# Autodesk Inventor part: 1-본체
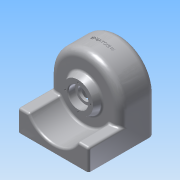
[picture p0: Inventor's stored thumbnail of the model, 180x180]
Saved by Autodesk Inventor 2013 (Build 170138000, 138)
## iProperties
Created: 2015-02
Part Number: 1-본체
Material: 알루미늄 6061
Document SubType Name: Modeling
Designer: Administrator
Density: 2.40731 g/cm^3
Mass: 511.244 g
Surface Area: 706.56 cm^2
Volume: 212.371 cm^3
Author: Administrator
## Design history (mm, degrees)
sketch "스케치1"
  geometry: L1 (-50, -50)-(50, -50); L2 (50, -50)-(50, 0); L3 (-50, 0)-(-50, -50); A1 r 50 centre (0, 0) between (50, 0) and (-50, 0); 1 further point
  constraints: 6 end point, 2 perpendicular, 2 point on circle, 1 centre point, 1 coincident, 1 horizontal, 1 parallel, 1 tangent
  dimensions: "d0" = 50 radius of A1; "d2" = 50 distance from line of L1 A1.centre
extrude "돌출1" new body sketch "스케치1" distance "d3" = 50; taper "d4" = 0 deg
fillet "모깎기1" dims "d5" = 10
feature "쉘1" dims "d6" = 4
node "작업 평면1"
sketch "스케치2"
  geometry: L1 (-50, 0)-(-50, -50) reference; L2 (50, -50)-(50, 0) reference; L3 (-40, -50)-(-50, -50) reference; L4 (-40, -50)-(40, -50) reference; L5 (50, -50)-(40, -50) reference; L6 (-40, -20)-(-34.641, -20); L7 (50, -20)-(34.641, -20); L8 (-34.641, -20)-(-50, -20); A1 r 40 centre (0, 0) between (-34.641, -20) and (34.641, -20); 1 further point
  constraints: 6 end point, 3 point on line, 2 point on circle, 1 centre point, 1 coincident, 1 collinear
  dimensions: "d8" = 40 radius of A1; "d11" = 30 distance between parallel lines of L4 L7; "d12" = 90 distance from line of L6.start L2
extrude "돌출2" join sketch "스케치2" stored distance "d13" = 50; taper "d14" = 0 deg
sketch "스케치3"
  geometry: C1 r 25 at (0, 0); A1 r 40 centre (0, 0) between (-34.641, -20) and (34.641, -20) reference
  constraints: 1 centre point, 1 coincident
  dimensions: "d15" = 50 diameter of C1
extrude "돌출3" join sketch "스케치3" distance "d17" = 10; taper "d18" = -20 deg
sketch "스케치4"
  geometry: C1 r 20 at (0, 0); A1 r 40 centre (0, 0) between (40, 0) and (-40, 0) reference
  constraints: 1 centre point, 1 coincident
  dimensions: "d19" = 40 diameter of C1
extrude "돌출4" join sketch "스케치4" distance "d21" = 9; taper "d22" = 0 deg
hole "구멍1" diameter "d25" = 20; stored, may be unused: countersink angle "d29" = 90 deg, drill point angle "d31" = 118 deg; dims "d23" = 10, "d24" = 10, "d26" = 6, "d27" = 28, "d28" = 10, "d30" = 8
hole "구멍2" diameter "d34" = 20; stored, may be unused: countersink angle "d38" = 90 deg, drill point angle "d40" = 0 deg; dims "d32" = 10, "d33" = 10, "d35" = 6, "d36" = 28, "d37" = 8, "d39" = 10
sketch "스케치6"
  geometry: C1 r 14 at (0, 0) reference; C2 r 21.36 at (0, 0) reference; A1 r 18 centre (0, 0) between (0, 18) and (-18, 0); 2 further points
  constraints: 4 point on circle, 2 horizontal alignment, 2 vertical alignment, 1 centre point, 1 coincident
  dimensions: "d41" = 36 diameter of A1
hole "구멍3" sketch "스케치6" at (0, 18), (-18, 0), (18, 0), (0, -18) diameter "d43" = 2.459; stored, may be unused: countersink angle "d47" = 90 deg, drill point angle "d49" = 118 deg; dims "d44" = 6, "d45" = 28, "d46" = 8, "d48" = 9
sketch "스케치7"
  geometry: L1 (-10, 95)-(90, 95) reference; L2 (81.75, 53)-(-1.75, 53); L3 (-1.75, 53)-(-1.75, 86); L4 (-1.75, 86)-(81.75, 86); L5 (81.75, 86)-(81.75, 53); L6 (81.75, 53)-(-1.75, 86); L7 (-1.75, 53)-(81.75, 86); 8 further points
  constraints: 12 end point, 4 coincident, 4 midpoint, 2 parallel, 1 horizontal, 1 perpendicular, 1 vertical alignment
  dimensions: "d50" = 9 distance between parallel lines of L4 L1; "d51" = 33 distance of L4.end L2.start; "d52" = 83.5 distance of L3.end L4.end
hole "구멍4" sketch "스케치7" at (-1.75, 86), (81.75, 86), (81.75, 53), (-1.75, 53) diameter "d53" = 5.134; stored, may be unused: countersink angle "d57" = 90 deg, drill point angle "d59" = 118 deg; dims "d54" = 10, "d55" = 28, "d56" = 8, "d58" = 13
fillet "모깎기2" dims "d60" = 0.3, "d61" = 3
fillet "모깎기3" dims "d62" = 3
chamfer "모따기1" distance "d63" = 1; stored, may be unused: second distance "d64" = 2, angle "d65" = 45 deg
node "작업 평면2"
sketch "스케치8"
  geometry: L1 (-21.36, 60)-(21.36, 60) reference; L2 (40, 0)-(-40, 0) reference; 3 further points
  constraints: 1 midpoint, 1 vertical alignment, 1 other
  dimensions: "d66" = 25 distance from line of point (0, 25) L2
feature "엠보싱1" sketch "스케치8" dims "d0" = 50, "d2" = 50, "d67" = 0.5, "d68" = 0
node "솔리드1"
other parameters: "d7" = -95
